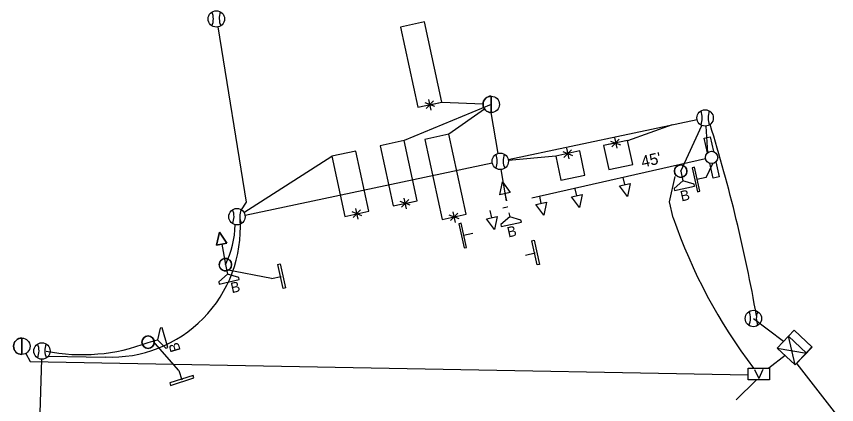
# Model space of a CAD drawing. Extents: x 596176 to 605330, y 332416 to 402398.
# Drawn here: x 604629.8 to 604829.9, y 339414.6 to 339509.2 of the extents above; entities that cross this region are included whole.
import ezdxf

# ---------------------------------------------------------------- set-up
doc = ezdxf.new("R2010")
doc.units = 0
for name, color, linetype in [('P_SIG', 7, 'Continuous'), ('P_SIG_Bold', 7, 'Continuous'), ('P_SIG_Conduit', 7, 'Continuous'), ('P_SIG_IC', 7, 'Continuous'), ('P_SIG_Loops', 7, 'Continuous'), ('P_SIG_SignalHeads', 7, 'Continuous')]:
    doc.layers.add(name, color=color, linetype=linetype)

# ---------------------------------------------------------------- blocks, each defined once
blk = doc.blocks.new('SIGNAL HEADS and POLES')
at = {"layer": 'P_SIG'}
blk.add_line((-15.42, 0.04), (0, 0), dxfattribs=at)
for points in [[(-24.44, 0.04), (-15.42, 4.05), (-15.42, -3.98), (-24.44, 0.04)], [(-15.42, 4.05), (-24.44, 0.04), (-15.42, -3.98), (-15.42, 4.05)]]:
    blk.add_lwpolyline(points, dxfattribs=at)
blk.add_circle((0, 0), 4.62, dxfattribs=at)
blk.add_circle((0, 0), 4.62, dxfattribs=at)
blk.add_circle((0, 0), 4.62, dxfattribs=at)
for start, end in [(0, 180), (180, 0)]:
    blk.add_arc((0, 0), 4.62, start, end, dxfattribs=at)
blk = doc.blocks.new('_U305')
at = {"layer": 'P_SIG_Loops'}
for p, q in [((-0.055, -0.084), (0.052, 0.081)), ((0.056, -0.083), (-0.053, 0.082)), ((0, 0), (0, -0.229)), ((-0.105, -0.001), (0.099, -0.001))]:
    blk.add_line(p, q, dxfattribs=at)
blk.add_lwpolyline([(0, -0.229), (1.524, -0.229), (1.524, 0.229), (0, 0.229)], close=True, dxfattribs=at)
blk = doc.blocks.new('_U310')
at = {"layer": 'P_SIG'}
blk.add_circle((0, 0), 4.62, dxfattribs=at)
for start, end in [(0, 180), (180, 0)]:
    blk.add_arc((0, 0), 4.62, start, end, dxfattribs=at)
blk = doc.blocks.new('_U226')
at = {"layer": 'P_SIG'}
blk.add_line((0.03, 6.11), (-0.03, -6.09), dxfattribs=at)
blk.add_lwpolyline([(-0.03, -6.09), (0.03, 6.11)], dxfattribs=at)
blk.add_circle((0, 0.01), 6.1, dxfattribs=at)
for start, end in [(89.70079, 180), (180, 269.70079)]:
    blk.add_arc((0, 0.01), 6.1, start, end, dxfattribs=at)
blk = doc.blocks.new('_U227')
at = {"layer": 'P_SIG'}
blk.add_circle((0, 0.01), 6.1, dxfattribs=at)
for centre, start, end in [((-15.46, 0.12), 336.67411, 22.52722), ((15.45, 0.15), 157.57508, 203.4282)]:
    blk.add_arc(centre, 13.28, start, end, dxfattribs=at)
blk = doc.blocks.new('CONTROL CABINET_1')
at = {"layer": 'P_SIG'}
for p, q in [((-0.229, 0.305), (0.229, 0.305)), ((-0.229, -0.152), (-0.229, 0.305)), ((0.229, 0.305), (0.229, -0.152)), ((-0.229, 0.152), (0.229, 0.152)), ((-0.229, -0.152), (0.229, 0.152)), ((0.229, -0.152), (-0.229, 0.152)), ((0.229, -0.152), (-0.229, -0.152))]:
    blk.add_line(p, q, dxfattribs=at)
blk = doc.blocks.new('HEAD - TEMPORARY_1')
at = {"layer": 'P_SIG'}
blk.add_line((5.4, 0), (0, 0), dxfattribs=at)
blk.add_lwpolyline([(14.41, 0), (5.4, -4.01), (5.4, 4.01)], close=True, dxfattribs=at)
blk = doc.blocks.new('_U316')
at = {"layer": 'P_SIG_Loops'}
for p, q in [((-0.055, -0.084), (0.052, 0.081)), ((0.056, -0.083), (-0.053, 0.082)), ((0, 0), (0, -0.229)), ((-0.105, -0.001), (0.099, -0.001))]:
    blk.add_line(p, q, dxfattribs=at)
blk.add_lwpolyline([(0, -0.229), (0.457, -0.229), (0.457, 0.229), (0, 0.229)], close=True, dxfattribs=at)
blk = doc.blocks.new('_U331')
at = {"layer": 'P_SIG_Bold'}
blk.add_line((-4.57, 0), (-137.16, 0), dxfattribs=at)
for points in [[(-2.29, 3.96), (-2.29, 15.24), (2.29, 15.24), (2.29, 3.96)], [(2.29, -3.96), (2.29, -15.24), (-2.29, -15.24), (-2.29, -3.96)]]:
    blk.add_lwpolyline(points, dxfattribs=at)
blk.add_circle((0, 0), 4.57, dxfattribs=at)
at = {"layer": 'P_SIG'}
blk.add_text("45'", height=8.534, dxfattribs=at).set_placement((-51.78, 3.96))
blk = doc.blocks.new('_U332')
at = {"layer": 'P_SIG_Bold'}
for p, q in [((-3.43, 0), (-0.11, 0)), ((-0.08, 0.08), (0.08, -0.08)), ((0.08, 0.08), (-0.08, -0.08))]:
    blk.add_line(p, q, dxfattribs=at)
blk.add_circle((0, 0), 0.114, dxfattribs=at)
blk.add_text("45'", height=0.213, dxfattribs=at).set_placement((-1.98, 0.09))
blk = doc.blocks.new('_U333')
at = {"layer": 'P_SIG_Loops'}
for p, q in [((-0.055, -0.084), (0.052, 0.081)), ((0.056, -0.083), (-0.053, 0.082)), ((0, 0), (0, -0.229)), ((-0.105, -0.001), (0.099, -0.001))]:
    blk.add_line(p, q, dxfattribs=at)
blk.add_lwpolyline([(0, -0.229), (1.143, -0.229), (1.143, 0.229), (0, 0.229)], close=True, dxfattribs=at)
blk = doc.blocks.new('CONTROL CABINET_2')
at = {"layer": 'P_SIG'}
for p, q in [((-0.229, 0.305), (0.229, 0.305)), ((-0.229, -0.152), (-0.229, 0.305)), ((0.229, 0.305), (0.229, -0.152)), ((-0.229, 0.152), (0.229, 0.152)), ((-0.229, -0.152), (0.229, 0.152)), ((0.229, -0.152), (-0.229, 0.152)), ((0.229, -0.152), (-0.229, -0.152))]:
    blk.add_line(p, q, dxfattribs=at)
blk = doc.blocks.new('COMMUNICATION VAULT')
at = {"layer": 'P_SIG'}
for p in [(-1.61, 1.65), (1.56, 1.65)]:
    blk.add_line(p, (-0.03, -1.65), dxfattribs=at)
blk.add_lwpolyline([(-3.98, 2.22), (3.98, 2.22), (3.98, -2.22), (-3.98, -2.22)], close=True, dxfattribs=at)

msp = doc.modelspace()

# ---------------------------------------------------------------- linework, layer by layer
at = {"layer": 'P_SIG'}
for p, q in [((604798.11, 339469.97), (604799.75, 339473.4)), ((604791.87, 339471.51), (604792.38, 339469.17)), ((604798.11, 339469.97), (604795.77, 339469.46)), ((604749.93, 339461.35), (604750.15, 339460.37)), ((604749.93, 339461.35), (604750.15, 339460.37)), ((604741.19, 339456.31), (604738.85, 339455.79)), ((604754.01, 339451.05), (604756.36, 339451.57)), ((604680.81, 339448.71), (604681.33, 339446.36)), ((604692.03, 339445.3), (604681.04, 339447.48)), ((604692.03, 339445.3), (604694.38, 339445.81)), ((604661.96, 339429.74), (604664.27, 339430.41)), ((604669.44, 339422.92), (604663.14, 339430.17)), ((604669.44, 339422.92), (604670.16, 339420.64))]:
    msp.add_line(p, q, dxfattribs=at)
for points in [[(604796.54, 339466.6), (604795.25, 339472.46), (604794.66, 339472.33), (604795.95, 339466.47)], [(604790.24, 339467.28), (604790.35, 339466.78), (604795.24, 339467.85), (604795.12, 339468.36), (604792.38, 339469.17)], [(604739.61, 339452.93), (604738.32, 339458.79), (604737.74, 339458.66), (604739.03, 339452.8)], [(604748, 339458.49), (604748.11, 339457.98), (604753, 339459.06), (604752.89, 339459.57), (604750.15, 339460.37)], [(604756.86, 339448.65), (604755.57, 339454.51), (604756.15, 339454.64), (604757.45, 339448.78)], [(604694.88, 339442.9), (604693.59, 339448.76), (604694.17, 339448.89), (604695.47, 339443.03)], [(604679.18, 339444.48), (604679.3, 339443.97), (604684.18, 339445.05), (604684.07, 339445.56), (604681.33, 339446.36)], [(604666.28, 339428.38), (604666.78, 339428.52), (604665.4, 339433.33), (604664.9, 339433.19), (604664.27, 339430.4)], [(604672.94, 339421.65), (604667.22, 339419.85), (604667.4, 339419.28), (604673.12, 339421.08)]]:
    msp.add_lwpolyline(points, close=True, dxfattribs=at)
for points in [[(604790.24, 339467.28), (604790.35, 339466.78), (604795.24, 339467.85), (604795.12, 339468.36), (604792.38, 339469.17), (604790.24, 339467.28)], [(604748, 339458.49), (604748.11, 339457.98), (604753, 339459.06), (604752.89, 339459.57), (604750.15, 339460.37), (604748, 339458.49)], [(604679.18, 339444.48), (604679.3, 339443.97), (604684.18, 339445.05), (604684.07, 339445.56), (604681.33, 339446.36), (604679.18, 339444.48)], [(604666.28, 339428.38), (604666.78, 339428.52), (604665.4, 339433.33), (604664.9, 339433.19), (604664.27, 339430.4), (604666.28, 339428.38)]]:
    msp.add_lwpolyline(points, dxfattribs=at)
at = {"layer": 'P_SIG_Conduit'}
for p, q in [((604747.37, 339475.85), (604745.64, 339485.79)), ((604791.87, 339471.51), (604797, 339482.67)), ((604749.38, 339464.3), (604748.05, 339471.92)), ((604634.12, 339366.68), (604636, 339425.66)), ((604820.19, 339424.52), (604829.9, 339412.1))]:
    msp.add_line(p, q, dxfattribs=at)
for points in [[(604684.74, 339462.06), (604685.94, 339463.96), (604679.02, 339506.68)], [(604749.81, 339474.32), (604795.88, 339484.07)], [(604797.97, 339482.49), (604798.4, 339475.96)], [(604685.59, 339460.74), (604745.9, 339473.5)], [(604809.6, 339435.58), (604816.98, 339430.02)], [(604637.63, 339426.43), (604651.48, 339426.19)]]:
    msp.add_lwpolyline(points, dxfattribs=at)
for centre, radius, start, end in [((604436.12, 339370.24), 380.01, 10.0017, 17.2451), ((604652.88, 339457.74), 31.58, 267.4578, 3.525), ((604659.71, 339459.01), 23.49, 333.9623, 358.6145), ((604645.84, 339471.78), 45.02, 258.7415, 290.9796)]:
    msp.add_arc(centre, radius, start, end, dxfattribs=at)
at = {"layer": 'P_SIG_IC'}
for p, q in [((604633.19, 339425.06), (604808.3, 339421.87)), ((604805.41, 339415.71), (604810.27, 339420.58))]:
    msp.add_line(p, q, dxfattribs=at)
for points in [[(604790.05, 339460.16), (604789.11, 339464.05), (604790.53, 339470.21)], [(604632.12, 339427.07), (604633.19, 339425.06)], [(604817.37, 339426.53), (604813.34, 339423.49)]]:
    msp.add_lwpolyline(points, dxfattribs=at)
msp.add_arc((604913.3, 339502.41), 130.3, 198.9238, 217.2786, dxfattribs=at)
at = {"layer": 'P_SIG_Loops'}
for p, q in [((604745.65, 339487.79), (604724.43, 339478.95)), ((604733.63, 339488.36), (604743.65, 339487.89)), ((604744, 339486.66), (604735.32, 339480.54)), ((604778.95, 339479.01), (604789.91, 339482.89)), ((604685.34, 339461.42), (604706.78, 339475.14)), ((604761.38, 339475.16), (604749.84, 339474.09))]:
    msp.add_line(p, q, dxfattribs=at)

# ---------------------------------------------------------------- block references
at = {"layer": 'P_SIG'}
for name, p, xscale, yscale, rotation in [('_U331', (604799.42, 339474.86), 0.3280833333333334, 0.32808333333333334, 12.750691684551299), ('_U310', (604791.87, 339471.51), 0.32808333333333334, 0.32808333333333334, -79.47535112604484), ('_U332', (604749.61, 339462.81), 0.32808333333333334, 0.3280833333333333, 12.461291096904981), ('SIGNAL HEADS and POLES', (604680.81, 339448.71), 0.32808333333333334, 0.32808333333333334, -79.47535112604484), ('CONTROL CABINET_1', (604818.97, 339427.76), 13.123333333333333, 13.123333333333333, -43.09647648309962), ('CONTROL CABINET_2', (604818.98, 339427.76), 13.123333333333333, 13.123333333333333, -43.24909086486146), ('_U310', (604661.94, 339429.81), 0.32808333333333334, 0.32808333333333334, 180)]:
    msp.add_blockref(name, p, dxfattribs=dict(at, xscale=xscale, yscale=yscale, rotation=rotation))
at = {"layer": 'P_SIG_Conduit', "xscale": 0.32808333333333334, "yscale": 0.32808333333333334}
for name, p in [('_U227', (604678.59, 339508.63)), ('_U226', (604745.65, 339487.79)), ('_U227', (604797.83, 339484.48)), ('_U227', (604747.85, 339473.91)), ('_U227', (604683.62, 339460.4)), ('_U227', (604809.6, 339435.58)), ('_U227', (604636.05, 339427.65))]:
    msp.add_blockref(name, p, dxfattribs=at)
at = {"layer": 'P_SIG_IC'}
for name, p, xscale, yscale in [('_U226', (604631.14, 339428.81), 0.32808333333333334, 0.32808333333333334), ('COMMUNICATION VAULT', (604810.91, 339422.04), 0.6561666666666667, 0.6561666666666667)]:
    msp.add_blockref(name, p, dxfattribs=dict(at, xscale=xscale, yscale=yscale))
at = {"layer": 'P_SIG_Loops'}
for name, p, xscale, yscale, rotation in [('_U305', (604730.69, 339487.72), 13.123333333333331, 13.123333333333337, 102.18605092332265), ('_U333', (604724.66, 339463.66), 13.123333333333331, 13.123333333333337, 102.18605092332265), ('_U305', (604736.6, 339460.35), 13.123333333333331, 13.123333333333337, 102.18605092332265), ('_U316', (604775.99, 339478.37), 13.123333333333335, 13.123333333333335, -77.81394907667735), ('_U316', (604764.31, 339475.79), 13.123333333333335, 13.123333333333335, -77.81394907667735), ('_U333', (604712.88, 339461.11), 13.123333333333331, 13.123333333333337, 102.18605092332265)]:
    msp.add_blockref(name, p, dxfattribs=dict(at, xscale=xscale, yscale=yscale, rotation=rotation))
at = {"layer": 'P_SIG_SignalHeads', "xscale": 0.3280833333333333, "yscale": 0.3280833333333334}
for p, rotation in [((604749.38, 339464.3), 102.30178657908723), ((604777.85, 339469.97), -77.69821342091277), ((604766.15, 339467.23), -77.69821342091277), ((604757.48, 339465.37), -77.69821342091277), ((604745.41, 339461.89), -77.69821342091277)]:
    msp.add_blockref('HEAD - TEMPORARY_1', p, dxfattribs=dict(at, rotation=rotation))

# ---------------------------------------------------------------- texts
at = {"layer": 'P_SIG'}
for rotation, p in [(12.4446, (604792.08, 339464.11)), (12.4446, (604749.84, 339455.32)), (12.4446, (604682.39, 339441.75)), (106.0637, (604669.92, 339427.8))]:
    msp.add_text('B', height=2.52, rotation=rotation, dxfattribs=at).set_placement(p)

doc.saveas('drawing.dxf')
